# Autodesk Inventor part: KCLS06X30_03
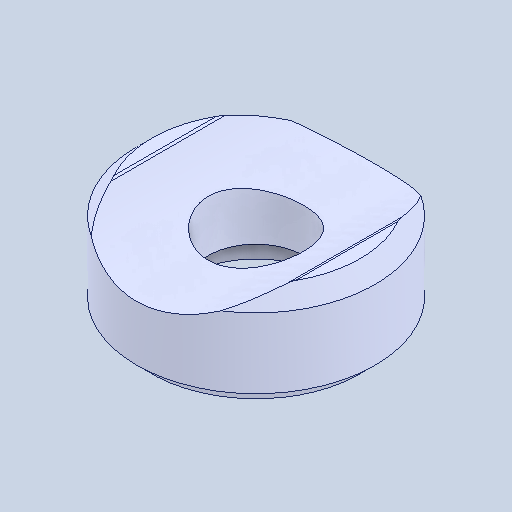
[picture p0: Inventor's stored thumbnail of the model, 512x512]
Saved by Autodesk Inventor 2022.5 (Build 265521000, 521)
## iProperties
Created: 2024-08
Part Number: KCLS06X30_03
Material: 一般
Document SubType Name: Modeling
Designer: ImaoCorp
Density: 1 g/cm^3
Appearance: 既定
Author: ImaoCorp
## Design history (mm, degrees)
feature "KCLS06X30_03"
node "ソリッド1"
